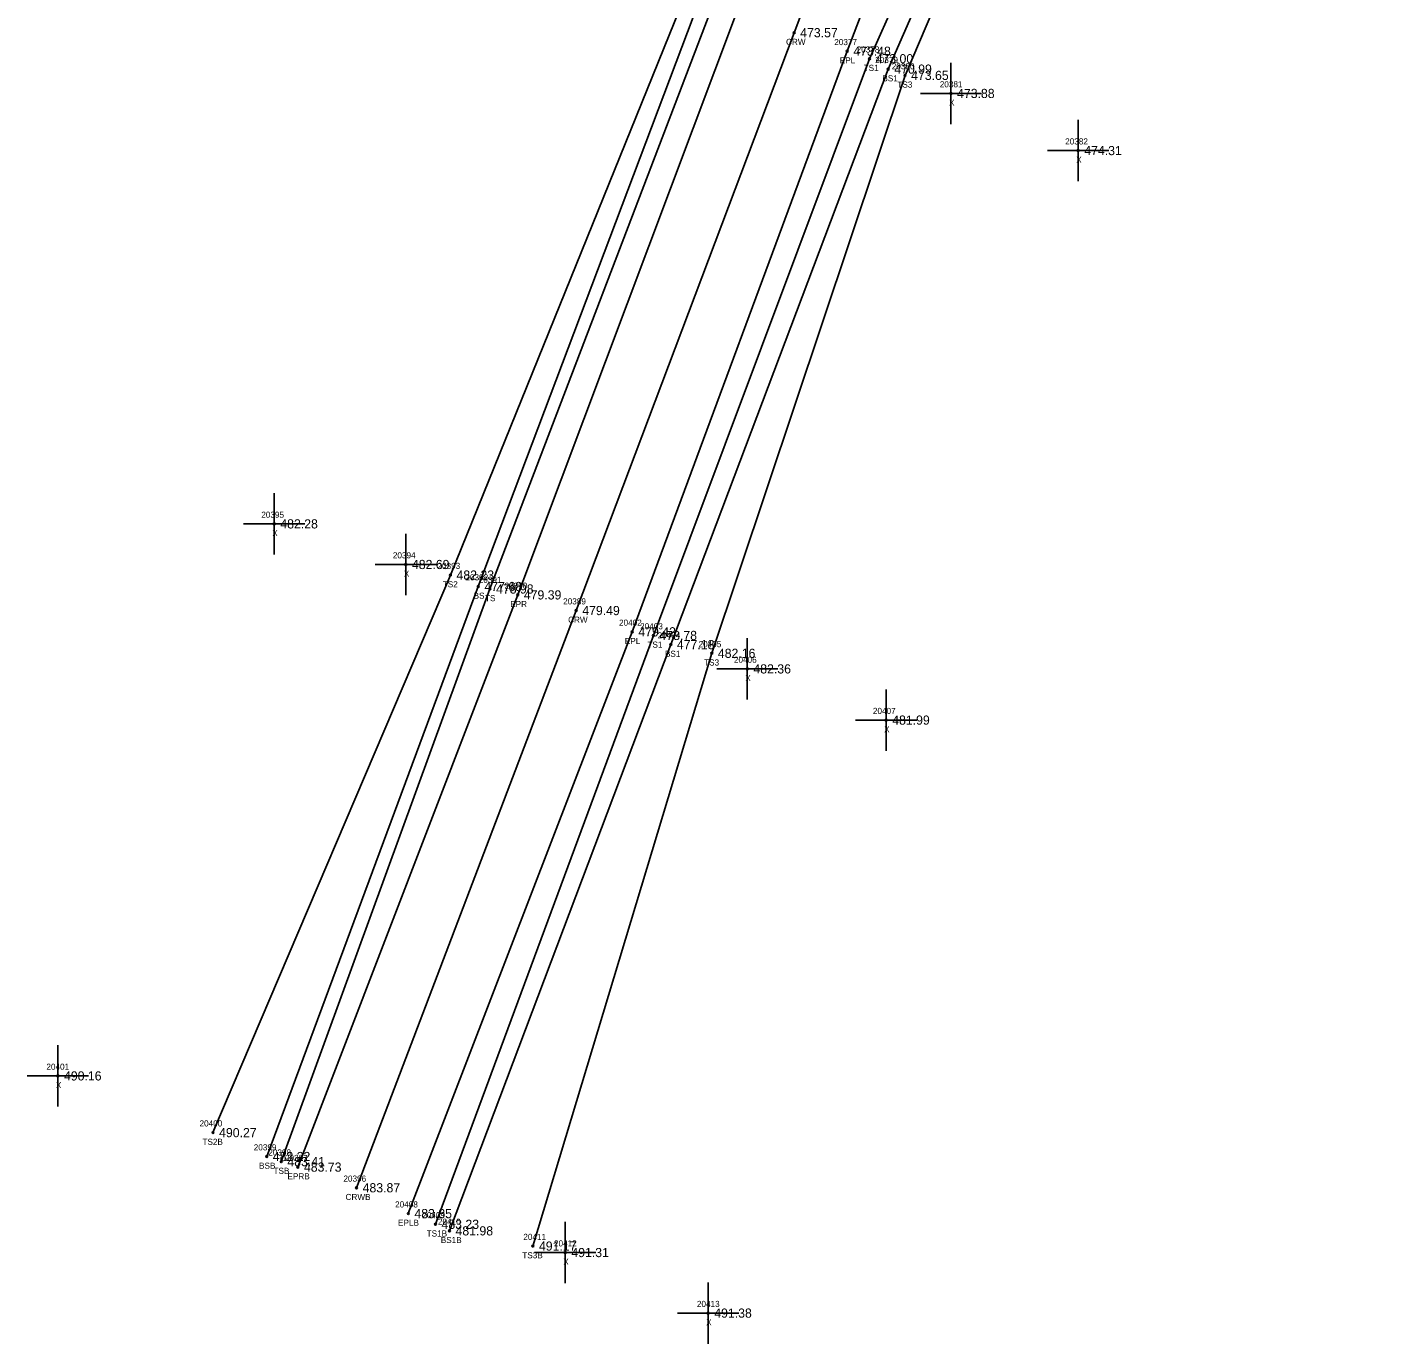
# Model space of a CAD drawing. Extents: x 1763022 to 1764007, y 824123 to 825394.
# Drawn here: x 1763136.1 to 1763359.3, y 824123.5 to 824338.7 of the extents above; entities that cross this region are included whole.
import ezdxf

# ---------------------------------------------------------------- set-up
doc = ezdxf.new("R2010")
doc.units = 0
for name, color, linetype in [('RD_DTM_BkLn1', 7, 'Continuous'), ('RD_DTM_BkLn2', 7, 'Continuous'), ('RD_DTM_BkLn_txCode', 7, 'Continuous'), ('RD_EX_Misc', 7, 'Continuous'), ('RD_EX_Misc_txCode', 7, 'Continuous'), ('RD_EX_Road', 7, 'Continuous'), ('RD_EX_Road_txCode', 7, 'Continuous'), ('RD_EX_TX_Misc_ELEV', 7, 'Continuous'), ('RD_EX_TX_Road_ELEV', 7, 'Continuous'), ('RD_HC_Survey_ELEV', 7, 'Continuous'), ('RD_HC_Survey_txCode', 7, 'Continuous'), ('RD_SMD_Locator', 7, 'Continuous')]:
    doc.layers.add(name, color=color, linetype=linetype)

msp = doc.modelspace()

# ---------------------------------------------------------------- linework, layer by layer
at = {"layer": 'RD_DTM_BkLn1'}
msp.add_lwpolyline([(1763465.6, 824795.18), (1763438.99, 824751.97), (1763414.16, 824707.73), (1763391.5, 824663.21), (1763370.27, 824618.19), (1763351.39, 824571.8), (1763333.36, 824525.39), (1763297, 824431.97), (1763261.49, 824337.79), (1763225.86, 824243.32), (1763189.96, 824148.95)], dxfattribs=at)
at = {"layer": 'RD_DTM_BkLn2'}
for points in [[(1763437.34, 824834), (1763430.66, 824820.06), (1763415.77, 824811.96), (1763415.35, 824798.51), (1763416.46, 824790.14), (1763418.19, 824781.43), (1763421.71, 824775.16), (1763417.19, 824763.87), (1763415.91, 824751.32), (1763399.06, 824714.58), (1763377.03, 824668.46), (1763355.81, 824623.79), (1763331.1, 824577.59), (1763312.25, 824532.84), (1763306.13, 824522.15), (1763306.75, 824510.59), (1763289.07, 824468.95), (1763279.57, 824438.1), (1763246.06, 824343.25), (1763209.87, 824247.25), (1763175.28, 824154.06)], [(1763453.01, 824802.49), (1763449.47, 824806.22), (1763441.02, 824809.92), (1763431.56, 824802.85), (1763425.71, 824792.63), (1763430.16, 824781.29), (1763430.95, 824776.81), (1763424.71, 824760.36), (1763418.93, 824749.28), (1763401.15, 824713.73), (1763378.81, 824667.77), (1763358.94, 824622.73), (1763337, 824576.46), (1763318.92, 824530.87), (1763314.75, 824518.63), (1763292.84, 824467.34), (1763282.85, 824437.24), (1763248.29, 824342.54), (1763211.77, 824246.85), (1763177.66, 824153.22)], [(1763350.33, 824535.07), (1763346.05, 824520.63), (1763338.21, 824498.94), (1763314.49, 824424.8), (1763273.82, 824333.54), (1763238.48, 824239.25), (1763202.86, 824142.98)], [(1763357.24, 824532.78), (1763354.57, 824517.79), (1763346.74, 824498.46), (1763344.14, 824496.19), (1763343.68, 824492.93), (1763346.46, 824491.28), (1763316.78, 824423.05), (1763276.87, 824331.84), (1763241.33, 824237.75), (1763205.15, 824141.91)], [(1763287.52, 824493.69), (1763288.06, 824469.58), (1763277.71, 824439.18), (1763243.74, 824344.03), (1763205.31, 824249.12), (1763166.5, 824157.97)], [(1763326.22, 824437.15), (1763318.69, 824422.62), (1763279.62, 824330.81), (1763248.03, 824236.33), (1763218.78, 824139.42)]]:
    msp.add_lwpolyline(points, dxfattribs=at)
at = {"layer": 'RD_EX_Misc'}
for p, q in [((1763287.13, 824322.86), (1763287.13, 824332.86)), ((1763282.13, 824327.86), (1763292.13, 824327.86)), ((1763307.92, 824313.52), (1763307.92, 824323.52)), ((1763302.92, 824318.52), (1763312.92, 824318.52)), ((1763176.51, 824252.49), (1763176.51, 824262.49)), ((1763171.51, 824257.49), (1763181.51, 824257.49)), ((1763198.02, 824245.85), (1763198.02, 824255.85)), ((1763193.02, 824250.85), (1763203.02, 824250.85)), ((1763253.84, 824228.78), (1763253.84, 824238.78)), ((1763248.84, 824233.78), (1763258.84, 824233.78)), ((1763276.53, 824220.41), (1763276.53, 824230.41)), ((1763271.53, 824225.41), (1763281.53, 824225.41)), ((1763141.15, 824162.24), (1763141.15, 824172.24)), ((1763136.15, 824167.24), (1763146.15, 824167.24)), ((1763224.08, 824133.36), (1763224.08, 824143.36)), ((1763219.08, 824138.36), (1763229.08, 824138.36)), ((1763247.44, 824123.46), (1763247.44, 824133.46)), ((1763242.44, 824128.46), (1763252.44, 824128.46))]:
    msp.add_line(p, q, dxfattribs=at)
at = {"layer": 'RD_EX_Road'}
for points in [[(1763458.16, 824800.38), (1763431, 824756.75), (1763406.01, 824711.9), (1763384.24, 824666.74), (1763362.81, 824620.84), (1763342.79, 824575), (1763324.89, 824528.78), (1763288.3, 824435.22), (1763252.09, 824341.05), (1763216.31, 824245.88), (1763180.37, 824152.33)], [(1763474.08, 824789.56), (1763447.08, 824747.55), (1763422.65, 824703.33), (1763399.6, 824659.26), (1763379.31, 824614.36), (1763364.49, 824579.4), (1763364.49, 824579.4), (1763359.36, 824568.52), (1763347.68, 824537.95), (1763341.79, 824522.26), (1763305.94, 824428.62), (1763270.17, 824334.76), (1763235.03, 824239.84), (1763198.43, 824144.73)]]:
    msp.add_lwpolyline(points, dxfattribs=at)
at = {"layer": 'RD_SMD_Locator'}
for centre in [(1763261.49, 824337.79), (1763270.17, 824334.76), (1763273.82, 824333.54), (1763276.87, 824331.84), (1763279.62, 824330.81), (1763287.13, 824327.86), (1763307.92, 824318.52), (1763176.51, 824257.49), (1763198.02, 824250.85), (1763205.31, 824249.12), (1763209.87, 824247.25), (1763211.77, 824246.85), (1763216.31, 824245.88), (1763225.86, 824243.32), (1763235.03, 824239.84), (1763238.48, 824239.25), (1763241.33, 824237.75), (1763248.03, 824236.33), (1763253.84, 824233.78), (1763276.53, 824225.41), (1763141.15, 824167.24), (1763166.5, 824157.97), (1763175.28, 824154.06), (1763177.66, 824153.22), (1763180.37, 824152.33), (1763189.96, 824148.95), (1763198.43, 824144.73), (1763202.86, 824142.98), (1763205.15, 824141.91), (1763218.78, 824139.42), (1763224.08, 824138.36), (1763247.44, 824128.46)]:
    msp.add_circle(centre, 0.15, dxfattribs=at)

# ---------------------------------------------------------------- texts
at = {"layer": 'RD_DTM_BkLn_txCode'}
for s, p in [('20378', (1763271.71, 824334.54)), ('20379', (1763274.75, 824332.84)), ('TS1', (1763272.86, 824331.54)), ('BS1', (1763275.92, 824329.84)), ('20380', (1763277.46, 824331.81)), ('TS3', (1763278.37, 824328.81)), ('20393', (1763203.19, 824250.12)), ('20392', (1763207.76, 824248.25)), ('20391', (1763209.94, 824247.85)), ('TS2', (1763204.06, 824247.12)), ('BS', (1763209.1, 824245.25)), ('TS', (1763210.97, 824244.85)), ('20403', (1763236.32, 824240.25)), ('20404', (1763239.17, 824238.75)), ('TS1', (1763237.52, 824237.25)), ('20405', (1763245.87, 824237.33)), ('BS1', (1763240.38, 824235.75)), ('TS3', (1763246.78, 824234.33)), ('20400', (1763164.3, 824158.97)), ('TS2B', (1763164.78, 824155.97)), ('20399', (1763173.16, 824155.06)), ('20398', (1763175.54, 824154.22)), ('BSB', (1763174.03, 824152.06)), ('TSB', (1763176.39, 824151.22)), ('20409', (1763200.71, 824143.98)), ('20410', (1763203.27, 824142.91)), ('TS1B', (1763201.43, 824140.98)), ('20411', (1763217.23, 824140.42)), ('BS1B', (1763203.73, 824139.91)), ('TS3B', (1763217.06, 824137.42))]:
    msp.add_text(s, height=1, dxfattribs=at).set_placement(p)
at = {"layer": 'RD_EX_Misc_txCode'}
for s, p in [('20381', (1763285.3, 824328.86)), ('X', (1763286.82, 824325.86)), ('20382', (1763305.8, 824319.52)), ('X', (1763307.6, 824316.52)), ('20395', (1763174.39, 824258.49)), ('X', (1763176.19, 824255.49)), ('20394', (1763195.9, 824251.85)), ('X', (1763197.7, 824248.85)), ('20406', (1763251.65, 824234.78)), ('X', (1763253.52, 824231.78)), ('20407', (1763274.37, 824226.41)), ('X', (1763276.21, 824223.41)), ('20401', (1763139.27, 824168.24)), ('X', (1763140.83, 824165.24)), ('20412', (1763222.24, 824139.36)), ('X', (1763223.76, 824136.36)), ('20413', (1763245.6, 824129.46)), ('X', (1763247.12, 824126.46))]:
    msp.add_text(s, height=1, dxfattribs=at).set_placement(p)
at = {"layer": 'RD_EX_Road_txCode'}
for s, p in [('20377', (1763268.05, 824335.76)), ('EPL', (1763268.96, 824332.76)), ('20390', (1763214.16, 824246.88)), ('EPR', (1763215.08, 824243.88)), ('20402', (1763232.87, 824240.84)), ('EPL', (1763233.82, 824237.84)), ('20397', (1763178.26, 824153.33)), ('EPRB', (1763178.67, 824150.33)), ('20408', (1763196.27, 824145.73)), ('EPLB', (1763196.75, 824142.73))]:
    msp.add_text(s, height=1, dxfattribs=at).set_placement(p)
at = {"layer": 'RD_EX_TX_Misc_ELEV'}
for s, p in [('473.00', (1763274.82, 824332.79)), ('470.99', (1763277.87, 824331.09)), ('473.65', (1763280.62, 824330.06)), ('473.88', (1763288.13, 824327.11)), ('474.31', (1763308.92, 824317.77)), ('482.28', (1763177.51, 824256.74)), ('482.69', (1763199.02, 824250.1)), ('482.23', (1763206.31, 824248.37)), ('477.68', (1763210.87, 824246.5)), ('478.98', (1763212.77, 824246.1)), ('478.78', (1763239.48, 824238.5)), ('477.18', (1763242.33, 824237)), ('482.16', (1763249.03, 824235.58)), ('482.36', (1763254.84, 824233.03)), ('481.99', (1763277.53, 824224.66)), ('490.16', (1763142.15, 824166.49)), ('490.27', (1763167.5, 824157.22)), ('482.22', (1763176.28, 824153.31)), ('483.41', (1763178.66, 824152.47)), ('483.23', (1763203.86, 824142.23)), ('481.98', (1763206.15, 824141.16)), ('491.17', (1763219.78, 824138.67)), ('491.31', (1763225.08, 824137.61)), ('491.38', (1763248.44, 824127.71))]:
    msp.add_text(s, height=1.5, dxfattribs=at).set_placement(p)
at = {"layer": 'RD_EX_TX_Road_ELEV'}
for s, p in [('473.48', (1763271.17, 824334.01)), ('479.39', (1763217.31, 824245.13)), ('479.42', (1763236.03, 824239.09)), ('483.73', (1763181.37, 824151.58)), ('483.85', (1763199.43, 824143.98))]:
    msp.add_text(s, height=1.5, dxfattribs=at).set_placement(p)
at = {"layer": 'RD_HC_Survey_ELEV'}
for s, p in [('473.57', (1763262.49, 824337.04)), ('479.49', (1763226.86, 824242.57)), ('483.87', (1763190.96, 824148.2))]:
    msp.add_text(s, height=1.5, dxfattribs=at).set_placement(p)
at = {"layer": 'RD_HC_Survey_txCode'}
for s, p in [('CRW', (1763260.17, 824335.79)), ('20389', (1763223.74, 824244.32)), ('CRW', (1763224.55, 824241.32)), ('20396', (1763187.82, 824149.95)), ('CRWB', (1763188.17, 824146.95))]:
    msp.add_text(s, height=1, dxfattribs=at).set_placement(p)

doc.saveas('drawing.dxf')
